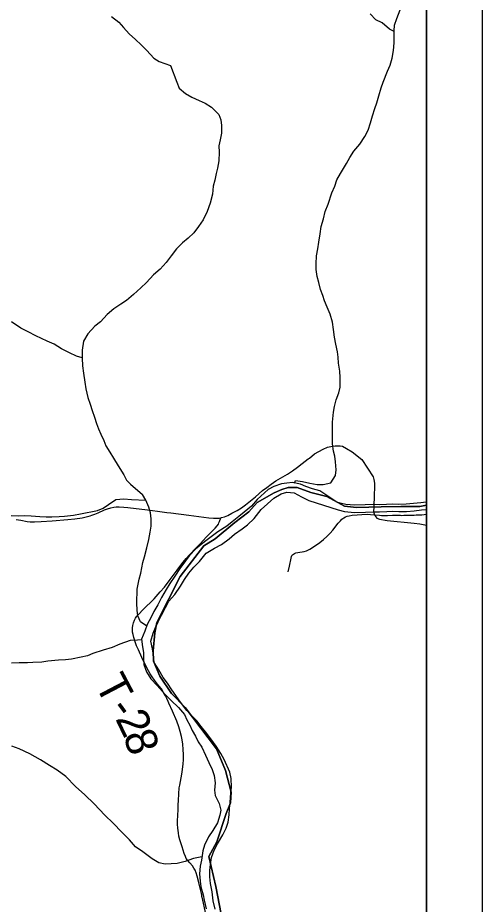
# Model space of a CAD drawing. Extents: x 0 to 34, y 0 to 22.
# Drawn here: x 8.379 to 9.214, y 17.022 to 18.618 of the extents above; entities that cross this region are included whole.
import ezdxf

# ---------------------------------------------------------------- set-up
doc = ezdxf.new("R2010")
doc.units = 0
for name, color, linetype in [('Default', 7, 'Continuous'), ('GM_X_County_Road', 7, 'Continuous'), ('GM_X_Minor_River', 7, 'Continuous'), ('GM_X_Township_Road', 7, 'Continuous'), ('GM_X_Township_Road_Text', 7, 'Continuous'), ('SH_Cut_Line', 7, 'Continuous'), ('SH_Data', 7, 'Continuous')]:
    doc.layers.add(name, color=color, linetype=linetype)

msp = doc.modelspace()

# ---------------------------------------------------------------- linework, layer by layer
at = {"layer": 'Default'}
for points in [[(8.7536, 16.957), (8.735, 17.0537), (8.7222, 17.1079), (8.7365, 17.1341), (8.7535, 17.185), (8.7613, 17.2043), (8.7624, 17.2236), (8.7521, 17.2629), (8.7361, 17.3016), (8.6795, 17.3759), (8.6551, 17.4016), (8.6342, 17.4327), (8.6229, 17.4596), (8.6224, 17.478), (8.625, 17.5105), (8.629, 17.5289), (8.6707, 17.6123), (8.7131, 17.6675), (8.7337, 17.6799), (8.7692, 17.7091), (8.7944, 17.7287), (8.8094, 17.7451), (8.84, 17.7629), (8.8537, 17.7689), (8.8651, 17.7725), (8.8815, 17.7721), (8.9057, 17.7634), (8.9349, 17.7561), (8.9664, 17.7387), (8.9879, 17.736), (9.0325, 17.7372), (9.0677, 17.7378), (9.102, 17.7378), (9.1142, 17.7402), (9.1142, 20.5497)], [(9.1142, 14.0996), (9.1142, 17.7402), (9.102, 17.7378), (9.0677, 17.7378), (9.0325, 17.7372), (8.9879, 17.736), (8.9664, 17.7387), (8.9349, 17.7561), (8.9057, 17.7634), (8.8815, 17.7721), (8.8651, 17.7725), (8.8537, 17.7689), (8.84, 17.7629), (8.8094, 17.7451), (8.7944, 17.7287), (8.7692, 17.7091), (8.7337, 17.6799), (8.7131, 17.6675), (8.6707, 17.6123), (8.629, 17.5289), (8.625, 17.5105), (8.6224, 17.478), (8.6229, 17.4596), (8.6342, 17.4327), (8.6551, 17.4016), (8.6795, 17.3759), (8.7361, 17.3016), (8.7521, 17.2629), (8.7624, 17.2236), (8.7613, 17.2043), (8.7535, 17.185), (8.7365, 17.1341), (8.7222, 17.1079), (8.735, 17.0537), (8.7536, 16.957)]]:
    msp.add_lwpolyline(points, dxfattribs=at)
at = {"layer": 'GM_X_County_Road'}
for points in [[(8.9033, 17.8252), (8.9122, 17.8328), (8.9282, 17.8416), (8.9361, 17.845), (8.9421, 17.8463), (8.9496, 17.8471), (8.9588, 17.8472), (8.9626, 17.8466), (8.9703, 17.8427), (8.9803, 17.8368), (8.9975, 17.8225), (9.0177, 17.7914), (9.0194, 17.7868), (9.0204, 17.78), (9.0204, 17.7725), (9.0198, 17.7588), (9.019, 17.7369)], [(8.7439, 17.7177), (8.7454, 17.718), (8.7506, 17.7197), (8.7563, 17.722), (8.764, 17.7259), (8.7732, 17.731), (8.7811, 17.7359), (8.7881, 17.7409), (8.7974, 17.7481), (8.8064, 17.7557), (8.8191, 17.7667), (8.8264, 17.7725), (8.8345, 17.7784), (8.8428, 17.784), (8.8513, 17.7891), (8.8636, 17.7964), (8.8729, 17.8025), (8.882, 17.8089), (8.8904, 17.8153), (8.9012, 17.8237), (8.9033, 17.8252)], [(8.3759, 17.7147), (8.384, 17.7135), (8.3955, 17.7113), (8.401, 17.7106), (8.409, 17.7104), (8.4207, 17.7108), (8.4404, 17.712), (8.4688, 17.7145), (8.4816, 17.7161), (8.4945, 17.7178), (8.5017, 17.7194), (8.5088, 17.7213), (8.5117, 17.7222), (8.5174, 17.7244), (8.5231, 17.7269), (8.5345, 17.7318), (8.5398, 17.7337), (8.5458, 17.7354), (8.5513, 17.7366), (8.5557, 17.7372), (8.5613, 17.7374), (8.5695, 17.737), (8.5769, 17.7362), (8.612, 17.7321), (8.6299, 17.7299), (8.6471, 17.7275), (8.6539, 17.7265), (8.6865, 17.7224), (8.7222, 17.7179), (8.7309, 17.7171), (8.737, 17.7169), (8.7412, 17.7172), (8.7439, 17.7177)], [(9.019, 17.7369), (9.0187, 17.729), (9.0189, 17.7266), (9.0203, 17.7231), (9.0208, 17.7216), (9.0247, 17.7172), (9.0295, 17.715), (9.043, 17.7129), (9.0918, 17.7082)], [(9.0918, 17.7082), (9.1021, 17.7066), (9.1142, 17.7045)]]:
    msp.add_lwpolyline(points, dxfattribs=at)
at = {"layer": 'GM_X_Minor_River'}
for points in [[(8.8767, 17.7803), (8.8782, 17.7847), (8.8911, 17.783), (8.9043, 17.7798), (8.9172, 17.7777), (8.9282, 17.7776), (8.9419, 17.7808), (8.95, 17.794), (8.9512, 17.8038), (8.9503, 17.8182), (8.9489, 17.8285), (8.9464, 17.838), (8.945, 17.8509), (8.9448, 17.8638), (8.9446, 17.8775), (8.9447, 17.89), (8.9465, 17.9078), (8.9485, 17.9184), (8.9513, 17.9301), (8.956, 17.9429), (8.9584, 17.9532), (8.9586, 17.9702), (8.958, 17.982), (8.9559, 17.996), (8.9549, 18.0071), (8.9539, 18.0166), (8.9511, 18.0306), (8.9482, 18.0428), (8.9468, 18.0565), (8.9451, 18.0701), (8.9404, 18.0846), (8.9352, 18.0968), (8.9304, 18.1083), (8.9275, 18.1182), (8.9235, 18.1288), (8.9202, 18.1414), (8.9173, 18.1524), (8.9156, 18.1646), (8.9154, 18.1748), (8.9163, 18.1892), (8.9183, 18.2021), (8.9204, 18.2142), (8.9229, 18.2293), (8.9242, 18.2422), (8.9285, 18.2562), (8.9317, 18.2694), (8.9372, 18.2822), (8.9439, 18.3026), (8.949, 18.3151), (8.9529, 18.3264), (8.9591, 18.3377), (8.9703, 18.3558), (8.9761, 18.3663), (8.9835, 18.3776), (8.9939, 18.3907), (9.0032, 18.4043), (9.009, 18.4159), (9.0133, 18.4288), (9.0165, 18.4416), (9.0212, 18.4548), (9.0244, 18.4647), (9.028, 18.4775), (9.0323, 18.4922), (9.0362, 18.5024), (9.0437, 18.5217), (9.0484, 18.5326), (9.0523, 18.5451), (9.0544, 18.5591), (9.0557, 18.5727), (9.056, 18.5947), (9.0565, 18.6049), (9.0604, 18.6166), (9.0667, 18.6325)], [(8.5475, 18.6204), (8.5603, 18.61), (8.5689, 18.6004), (8.579, 18.5893), (8.5902, 18.5789), (8.6007, 18.5696), (8.6108, 18.5589), (8.6232, 18.5454), (8.6333, 18.5392), (8.6431, 18.5357), (8.6537, 18.5321), (8.6647, 18.5024), (8.6687, 18.4914), (8.6804, 18.4817), (8.6917, 18.4751), (8.7049, 18.4693), (8.7158, 18.4642), (8.7274, 18.4572), (8.7402, 18.4438), (8.7438, 18.4342), (8.7452, 18.424), (8.7451, 18.4103), (8.743, 18.3986), (8.7406, 18.3876), (8.7408, 18.3759), (8.7403, 18.3607), (8.7378, 18.3475), (8.7358, 18.3376), (8.733, 18.3259), (8.7302, 18.3146), (8.7289, 18.3006), (8.7249, 18.2843), (8.7194, 18.2692), (8.712, 18.2545), (8.7035, 18.2421), (8.6954, 18.2308), (8.685, 18.2215), (8.6751, 18.2129), (8.6643, 18.202), (8.6547, 18.1897), (8.6458, 18.1776), (8.6347, 18.1653), (8.6228, 18.1552), (8.6101, 18.1417), (8.5998, 18.132), (8.5867, 18.1196), (8.5741, 18.1092), (8.5641, 18.1025), (8.5515, 18.0939), (8.5392, 18.0839), (8.5273, 18.0707), (8.517, 18.0625), (8.5047, 18.0487), (8.4969, 18.0359), (8.4945, 18.0196), (8.4947, 18.0052), (8.4952, 17.9911), (8.4966, 17.9782), (8.4994, 17.9619), (8.5012, 17.9497), (8.5044, 17.9341), (8.5088, 17.9223), (8.5124, 17.9109), (8.5164, 17.8991), (8.5205, 17.8876), (8.5241, 17.8781), (8.5282, 17.8686), (8.5337, 17.8571)], [(9.056, 18.5936), (9.0473, 18.5975), (9.0342, 18.609), (9.0229, 18.6145), (9.0124, 18.6249)], [(8.4946, 18.0057), (8.4841, 18.0087), (8.4717, 18.015), (8.4573, 18.022), (8.4442, 18.0301), (8.4317, 18.0356), (8.4212, 18.0407), (8.4114, 18.0453), (8.3971, 18.0524), (8.3839, 18.0594), (8.3673, 18.0706)], [(8.5337, 17.8571), (8.537, 17.8476), (8.5441, 17.8361), (8.5508, 17.8251), (8.5593, 17.8113), (8.5694, 17.7952), (8.5742, 17.7857), (8.5816, 17.7783), (8.6029, 17.7596)], [(8.9526, 17.746), (8.922, 17.7663), (8.9091, 17.7699), (8.897, 17.7738), (8.8872, 17.7785), (8.8729, 17.781), (8.8626, 17.78), (8.8531, 17.7786), (8.839, 17.7738), (8.8291, 17.7687), (8.8091, 17.7505)], [(8.3665, 17.7216), (8.3806, 17.7214), (8.3908, 17.7216), (8.4026, 17.7215), (8.4181, 17.7201), (8.4295, 17.7195), (8.4401, 17.7194), (8.4533, 17.72), (8.4628, 17.7206), (8.4788, 17.7226), (8.4913, 17.7251), (8.5218, 17.7307), (8.5321, 17.7352), (8.542, 17.7419), (8.555, 17.7508), (8.5695, 17.7517), (8.5835, 17.7504), (8.6089, 17.7492)], [(8.6106, 17.5227), (8.5996, 17.5302), (8.5948, 17.5409), (8.5935, 17.5515), (8.5929, 17.5641), (8.5933, 17.5892), (8.5969, 17.6073), (8.6001, 17.6183), (8.6038, 17.6373), (8.6066, 17.6475), (8.6106, 17.6634), (8.6143, 17.6789), (8.6167, 17.6918), (8.6184, 17.7028), (8.6186, 17.7157), (8.6173, 17.7267), (8.6144, 17.737), (8.6089, 17.7492), (8.6029, 17.7596)], [(8.7335, 17.0131), (8.7303, 17.028), (8.7283, 17.0443), (8.7255, 17.0592), (8.7241, 17.0714), (8.7243, 17.0824), (8.7252, 17.0934), (8.7273, 17.1059), (8.7317, 17.1191), (8.7379, 17.1308), (8.7476, 17.147), (8.7535, 17.1591), (8.7574, 17.1697), (8.7587, 17.1829), (8.7597, 17.1936), (8.7606, 17.2057), (8.762, 17.2217), (8.7633, 17.2326), (8.7627, 17.2482), (8.7602, 17.2597), (8.75, 17.2826), (8.7437, 17.2933), (8.7355, 17.3064), (8.7262, 17.3198), (8.7188, 17.3294), (8.7087, 17.3417), (8.7013, 17.3513), (8.6919, 17.3609), (8.683, 17.3709), (8.6714, 17.3855), (8.6629, 17.3978), (8.6558, 17.4078), (8.6481, 17.4197), (8.6402, 17.4304), (8.6325, 17.4439), (8.624, 17.4573), (8.6226, 17.4698), (8.6209, 17.482), (8.6181, 17.4953), (8.6221, 17.5097), (8.6264, 17.5199), (8.6315, 17.5305), (8.6373, 17.5426), (8.6444, 17.5565), (8.6506, 17.5678), (8.661, 17.5798), (8.6711, 17.5949), (8.6788, 17.6069), (8.6866, 17.6178), (8.6955, 17.6287), (8.7055, 17.6392), (8.7178, 17.6538), (8.7324, 17.6631), (8.745, 17.6698), (8.7588, 17.6798), (8.7687, 17.6881), (8.7822, 17.6977), (8.7917, 17.7048), (8.804, 17.7164), (8.8168, 17.7326), (8.8395, 17.753)], [(8.8395, 17.753), (8.8525, 17.7608), (8.8624, 17.7637), (8.8757, 17.7627), (8.8888, 17.7553), (8.9024, 17.7487)], [(8.8091, 17.7505), (8.7994, 17.7389), (8.786, 17.7277), (8.7764, 17.7199), (8.7645, 17.7102), (8.7545, 17.7027), (8.7385, 17.6923), (8.7289, 17.6852), (8.7143, 17.6744), (8.6986, 17.6613), (8.6878, 17.6501), (8.6801, 17.6403), (8.6704, 17.6264), (8.6611, 17.6129), (8.6522, 17.5993), (8.6456, 17.5884), (8.6374, 17.5741), (8.6308, 17.5609), (8.6234, 17.5492), (8.6187, 17.539), (8.6117, 17.5255), (8.607, 17.5137), (8.6011, 17.4994), (8.6031, 17.4853), (8.6049, 17.4754), (8.6051, 17.4655), (8.6057, 17.4534), (8.6104, 17.4404), (8.6182, 17.4277), (8.6294, 17.4158), (8.6432, 17.4004), (8.6548, 17.3888), (8.6675, 17.3761), (8.6783, 17.3634), (8.6827, 17.3539), (8.6879, 17.3443), (8.6923, 17.3347), (8.6982, 17.3244), (8.703, 17.3141), (8.7097, 17.3045), (8.7163, 17.2903), (8.7226, 17.2773), (8.7285, 17.2647), (8.7321, 17.2536), (8.7338, 17.2403), (8.7325, 17.2274), (8.7338, 17.2175), (8.7412, 17.2033), (8.7437, 17.1915), (8.742, 17.182), (8.7381, 17.1684), (8.7295, 17.1549), (8.7218, 17.1432), (8.7147, 17.1281), (8.7115, 17.1179), (8.709, 17.1012), (8.707, 17.0902), (8.7056, 17.0766), (8.7066, 17.0633), (8.7079, 17.053), (8.7119, 17.0389), (8.714, 17.0294), (8.7176, 17.0137)], [(8.9024, 17.7487), (8.9549, 17.7318), (8.9666, 17.7288), (8.9843, 17.7275), (9.004, 17.728), (9.0181, 17.7285), (9.0294, 17.7284), (9.0423, 17.7289), (9.053, 17.7296), (9.064, 17.729), (9.078, 17.7292), (9.0917, 17.7305), (9.105, 17.7318), (9.1142, 17.7328)], [(9.1142, 17.7457), (9.1134, 17.7456), (9.1036, 17.7446), (9.0904, 17.7433), (9.0773, 17.742), (9.0642, 17.7419), (9.0529, 17.7424), (9.0417, 17.7418), (9.0293, 17.7412), (9.0179, 17.7414), (9.0036, 17.7408), (8.9846, 17.7404), (8.9686, 17.7416), (8.9584, 17.7441), (8.9526, 17.746)], [(8.6013, 17.4977), (8.5938, 17.4976), (8.5809, 17.497), (8.5622, 17.4901), (8.5485, 17.4842), (8.5325, 17.4795), (8.5138, 17.4733), (8.5043, 17.4693), (8.4929, 17.4668), (8.4754, 17.4632), (8.4644, 17.4622), (8.4522, 17.4613), (8.4325, 17.4593), (8.4219, 17.4579), (8.4059, 17.457), (8.3961, 17.4564), (8.3809, 17.4566), (8.3676, 17.456)], [(8.7099, 17.1073), (8.695, 17.1041), (8.6798, 17.0986), (8.6653, 17.0954), (8.6547, 17.0944), (8.6441, 17.0942), (8.6324, 17.0966), (8.6203, 17.1036), (8.6034, 17.116), (8.5903, 17.125), (8.5795, 17.1377), (8.5657, 17.1515), (8.55, 17.1677), (8.5354, 17.1824), (8.516, 17.2024), (8.4991, 17.2186), (8.4823, 17.234), (8.4651, 17.2518), (8.4494, 17.263), (8.4358, 17.2716), (8.4197, 17.2817), (8.4001, 17.293), (8.3813, 17.302), (8.3677, 17.3067)]]:
    msp.add_lwpolyline(points, dxfattribs=at)
at = {"layer": 'GM_X_Township_Road'}
for points in [[(8.8651, 17.6207), (8.8676, 17.6309), (8.8703, 17.645), (8.8711, 17.648), (8.8718, 17.6497), (8.873, 17.6511), (8.8744, 17.6523), (8.8766, 17.6536), (8.8789, 17.6545), (8.8825, 17.6553), (8.8941, 17.6568), (8.898, 17.6584), (8.9003, 17.6594), (8.9041, 17.6614), (8.9125, 17.6668), (8.9218, 17.6735), (8.9286, 17.6789), (8.9347, 17.6842), (8.9408, 17.6903), (8.9454, 17.6955), (8.9553, 17.7082), (8.959, 17.7124), (8.9617, 17.715), (8.9651, 17.7175), (8.9684, 17.7192), (8.9713, 17.7204), (8.9749, 17.7213), (8.9804, 17.7223), (8.989, 17.7233), (8.9977, 17.7238), (9.0081, 17.724), (9.0134, 17.7236), (9.0203, 17.7231)], [(9.0203, 17.7231), (9.0213, 17.723), (9.0296, 17.7222), (9.0332, 17.7219)], [(9.0332, 17.7219), (9.0435, 17.722), (9.0527, 17.7222), (9.0576, 17.7222), (9.0644, 17.7222), (9.0669, 17.7222), (9.0693, 17.7221), (9.073, 17.7222), (9.0767, 17.7222), (9.081, 17.7223), (9.0835, 17.7223), (9.0915, 17.7226), (9.0952, 17.7228), (9.0983, 17.7229), (9.1032, 17.7231), (9.1057, 17.7233), (9.1142, 17.7241)], [(8.7167, 17.0044), (8.7101, 17.0344), (8.7097, 17.0351), (8.7095, 17.0363), (8.7095, 17.0373), (8.7096, 17.0381), (8.709, 17.0415), (8.7057, 17.0559), (8.7039, 17.0632), (8.7016, 17.0722), (8.6995, 17.0786), (8.6975, 17.0832), (8.6955, 17.0869), (8.6927, 17.091), (8.6883, 17.0962), (8.6839, 17.1015), (8.6818, 17.1045), (8.6801, 17.1078), (8.678, 17.113), (8.6741, 17.1254), (8.6703, 17.1379), (8.6686, 17.1445), (8.6675, 17.1506), (8.6664, 17.1586), (8.6659, 17.166), (8.6659, 17.1723), (8.6665, 17.1816), (8.6671, 17.1927), (8.6672, 17.2008), (8.6675, 17.2089), (8.6681, 17.2206), (8.6692, 17.2312), (8.6699, 17.2361), (8.6738, 17.2562), (8.6751, 17.2642), (8.6764, 17.2746), (8.6768, 17.2821), (8.6769, 17.2914), (8.6764, 17.3007), (8.6756, 17.31), (8.6744, 17.318), (8.6732, 17.3241), (8.6708, 17.3331), (8.6681, 17.3414), (8.6645, 17.3513), (8.6569, 17.3697), (8.6507, 17.3839), (8.6495, 17.3867), (8.647, 17.3924), (8.6445, 17.3974), (8.6411, 17.4033), (8.637, 17.4096), (8.6333, 17.4145), (8.6302, 17.4184), (8.6248, 17.4252), (8.6205, 17.4312), (8.6169, 17.437), (8.6137, 17.4423), (8.6072, 17.4549), (8.6017, 17.4661), (8.5956, 17.4797), (8.5925, 17.4871), (8.5898, 17.4946), (8.5873, 17.5022), (8.586, 17.5076), (8.5853, 17.5119), (8.585, 17.5156), (8.5851, 17.5193), (8.5857, 17.5236), (8.5869, 17.5284), (8.5887, 17.5331), (8.5907, 17.5369), (8.5931, 17.5406), (8.5962, 17.5444), (8.6037, 17.5519), (8.6239, 17.5721), (8.6351, 17.5845), (8.6424, 17.593), (8.6531, 17.6067), (8.6656, 17.6237), (8.6756, 17.6372), (8.6814, 17.6445), (8.6868, 17.6505), (8.6993, 17.6635), (8.7066, 17.6711), (8.7177, 17.6828), (8.7297, 17.6946), (8.7339, 17.6991), (8.7374, 17.7034), (8.7395, 17.7065), (8.7406, 17.7087), (8.7415, 17.711), (8.7439, 17.7177)]]:
    msp.add_lwpolyline(points, dxfattribs=at)
at = {"layer": 'SH_Cut_Line'}
msp.add_lwpolyline([(9.1142, 14.0996), (9.1142, 20.8996), (2.3142, 20.8996)], dxfattribs=at)
at = {"layer": 'SH_Data'}
for p, q in [((9.2142, 20.9996), (9.2142, 13.9996)), ((9.1142, 20.8996), (9.1142, 14.0996))]:
    msp.add_line(p, q, dxfattribs=at)

# ---------------------------------------------------------------- texts
at = {"layer": 'GM_X_Township_Road_Text'}
for s, rotation, p in [('T', 297.7208, (8.5163, 17.418)), ('-', 306.4375, (8.5411, 17.3724)), ('2', 295.5748, (8.5535, 17.3561)), ('8', 288.0968, (8.5679, 17.3263))]:
    msp.add_text(s, height=0.0568, rotation=rotation, dxfattribs=at).set_placement(p)

doc.saveas('drawing.dxf')
